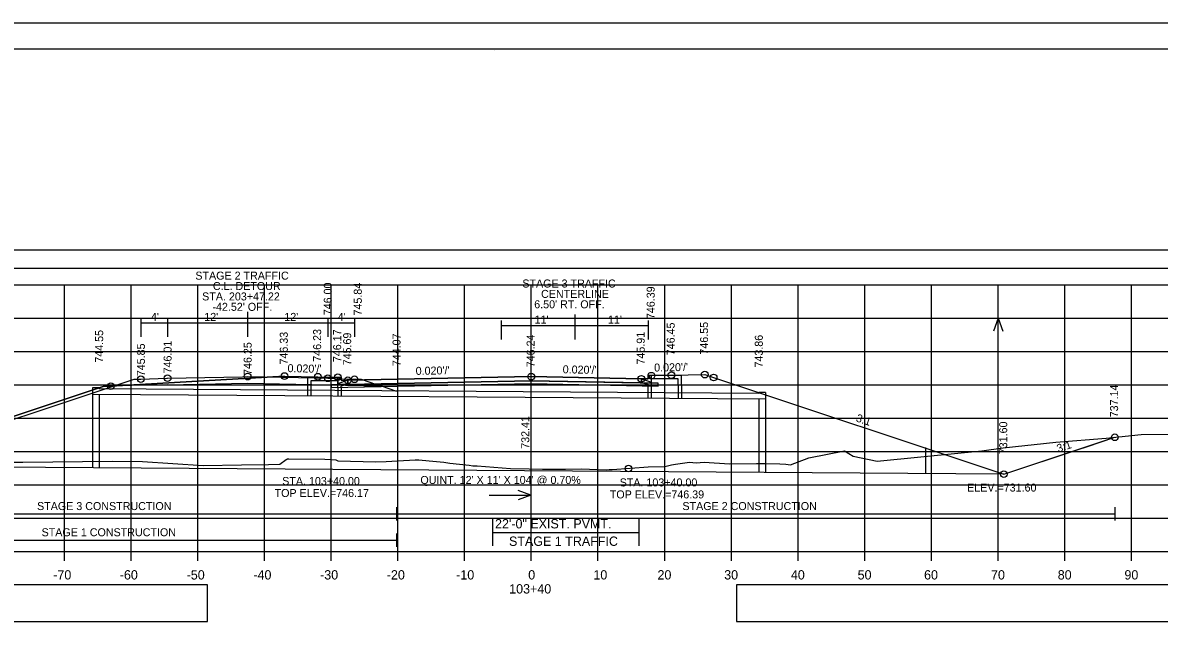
# Model space of a CAD drawing. Extents: x 1202951 to 1376887, y 378065 to 728038.
# Drawn here: x 1376508.4 to 1376678.8, y 378956.7 to 379047.8 of the extents above; entities that cross this region are included whole.
import ezdxf

# ---------------------------------------------------------------- set-up
doc = ezdxf.new("R2010")
doc.units = 0
for name, color, linetype in [('Default', 7, 'Continuous'), ('R_Alt Surface', 7, 'Continuous'), ('R_Axis', 7, 'Continuous'), ('R_Axis Annot', 7, 'Continuous'), ('R_Border', 7, 'Continuous'), ('R_Border Notes', 7, 'Continuous'), ('R_Detour', 7, 'Continuous'), ('R_Detour Annot', 7, 'Continuous'), ('R_Dimension', 7, 'Continuous'), ('R_Exist Surface', 7, 'Continuous'), ('R_Fin Surface', 7, 'Continuous'), ('R_Grid', 7, 'Continuous'), ('R_MOT', 7, 'Continuous'), ('R_No Plot', 7, 'Continuous'), ('R_Proposed Const Limits', 7, 'Continuous'), ('R_Water', 7, 'Continuous'), ('R_Water Annot', 7, 'Continuous'), ('R_Xsect Elev', 7, 'Continuous'), ('R_Xsect Slope', 7, 'Continuous')]:
    doc.layers.add(name, color=color, linetype=linetype)

msp = doc.modelspace()

# ---------------------------------------------------------------- linework, layer by layer
at = {"layer": 'Default'}
for points in [[(1376547.67, 378994.82), (1376521.65, 378993.29), (1376520.65, 378993.29), (1376484.65, 378981.29)], [(1376610.67, 378995.04), (1376612.01, 378994.6), (1376612.01, 378994.6), (1376655.52, 378980.09)]]:
    msp.add_lwpolyline(points, dxfattribs=at)
for points in [[(1376555.67, 378994.66), (1376556.16, 378994.66), (1376556.17, 378994.16), (1376557.17, 378994.18), (1376557.17, 378993.56), (1376555.67, 378993.53)], [(1376602.67, 378994.88), (1376602.18, 378994.88), (1376602.17, 378994.38), (1376601.17, 378994.4), (1376601.17, 378993.78), (1376602.67, 378993.75)]]:
    msp.add_lwpolyline(points, close=True, dxfattribs=at)
at = {"layer": 'R_Alt Surface'}
for q in [(1376554.67, 378993.51), (1376603.67, 378993.73)]:
    msp.add_line((1376584.67, 378994.11), q, dxfattribs=at)
for points in [[(1376434.67, 379010.99), (1376710.2, 379010.99), (1376710.2, 379013.7), (1376434.67, 379013.7)], [(1376584.67, 378994.11), (1376557.17, 378993.56), (1376555.67, 378993.53), (1376554.67, 378993.51), (1376554.67, 378993.09), (1376584.67, 378993.69), (1376603.67, 378993.31), (1376603.67, 378993.73), (1376602.67, 378993.75), (1376601.17, 378993.78)], [(1376557.17, 378994.18), (1376557.17, 378993.56), (1376584.67, 378994.11), (1376601.17, 378993.78), (1376601.17, 378994.4), (1376601.17, 378994.4), (1376584.67, 378994.73), (1376557.17, 378994.18)], [(1376434.67, 378957.97), (1376536.14, 378957.97), (1376536.14, 378963.49), (1376434.67, 378963.49)], [(1376615.43, 378957.97), (1376726.14, 378957.97), (1376726.14, 378963.49), (1376615.43, 378963.49)]]:
    msp.add_lwpolyline(points, close=True, dxfattribs=at)
msp.add_lwpolyline([(1376555.67, 378994.66), (1376555.67, 378993.53), (1376557.17, 378993.56), (1376584.67, 378994.11), (1376601.17, 378993.78), (1376602.67, 378993.75), (1376602.67, 378994.88)], dxfattribs=at)
at = {"layer": 'R_Axis'}
for p, q in [((1376434.67, 378968.49), (1376734.67, 378968.49)), ((1376514.67, 378967.09), (1376514.67, 378968.49)), ((1376524.67, 378967.09), (1376524.67, 378968.49)), ((1376534.67, 378967.09), (1376534.67, 378968.49)), ((1376544.67, 378967.09), (1376544.67, 378968.49)), ((1376554.67, 378967.09), (1376554.67, 378968.49)), ((1376564.67, 378967.09), (1376564.67, 378968.49)), ((1376574.67, 378967.09), (1376574.67, 378968.49)), ((1376584.67, 378967.09), (1376584.67, 378968.49)), ((1376594.67, 378967.09), (1376594.67, 378968.49)), ((1376604.67, 378967.09), (1376604.67, 378968.49)), ((1376614.67, 378967.09), (1376614.67, 378968.49)), ((1376624.67, 378967.09), (1376624.67, 378968.49)), ((1376634.67, 378967.09), (1376634.67, 378968.49)), ((1376644.67, 378967.09), (1376644.67, 378968.49)), ((1376654.67, 378967.09), (1376654.67, 378968.49)), ((1376664.67, 378967.09), (1376664.67, 378968.49)), ((1376674.67, 378967.09), (1376674.67, 378968.49))]:
    msp.add_line(p, q, dxfattribs=at)
at = {"layer": 'R_Border'}
for p, q in [((1376426.67, 379043.95), (1376742.85, 379043.95)), ((1376579.19, 379043.69), (1376579.19, 379043.69)), ((1376579.19, 379043.69), (1376579.19, 379043.69))]:
    msp.add_line(p, q, dxfattribs=at)
at = {"layer": 'R_Detour'}
for p, q in [((1376542.15, 379004.46), (1376542.15, 379000.7)), ((1376526.15, 379003.54), (1376526.15, 379000.7)), ((1376526.15, 379002.8), (1376530.15, 379002.8)), ((1376530.15, 379003.54), (1376530.15, 379000.7)), ((1376530.15, 379002.8), (1376542.15, 379002.8)), ((1376542.15, 379002.8), (1376554.15, 379002.8)), ((1376554.15, 379003.54), (1376554.15, 379000.7)), ((1376554.15, 379002.8), (1376558.15, 379002.8)), ((1376558.15, 379003.54), (1376558.15, 379000.7))]:
    msp.add_line(p, q, dxfattribs=at)
for points in [[(1376478.29, 378982.39), (1376480.46, 378981.67), (1376483.77, 378980.57), (1376494.76, 378984.23), (1376522.15, 378993.35), (1376524.97, 378994.29), (1376525.15, 378994.35), (1376526.1, 378994.35), (1376526.15, 378994.35), (1376530.06, 378994.5), (1376530.15, 378994.5), (1376532.95, 378994.56), (1376541.38, 378994.72), (1376542.15, 378994.74), (1376552.32, 378994.53), (1376554.16, 378994.49), (1376557.36, 378994.37), (1376558.16, 378994.33), (1376558.38, 378994.33), (1376559.16, 378994.33), (1376561.45, 378993.57), (1376562.17, 378993.33), (1376564.47, 378992.57)], [(1376530.15, 378993.5), (1376542.15, 378993.74), (1376554.16, 378993.49)], [(1376530.15, 378993.5), (1376522.15, 378993.35)], [(1376554.16, 378993.49), (1376562.17, 378993.33)]]:
    msp.add_lwpolyline(points, dxfattribs=at)
at = {"layer": 'R_Dimension'}
for points in [[(1376564.47, 378975.13), (1376564.47, 378973.13)], [(1376672.14, 378975.13), (1376672.14, 378973.13)], [(1376478.29, 378974.13), (1376564.47, 378974.13)], [(1376564.47, 378974.13), (1376672.14, 378974.13)], [(1376478.29, 378970.21), (1376564.47, 378970.21)], [(1376564.47, 378971.21), (1376564.47, 378969.21)]]:
    msp.add_lwpolyline(points, dxfattribs=at)
at = {"layer": 'R_Exist Surface'}
msp.add_lwpolyline([(1376505.03, 378981.9), (1376508.44, 378981.89), (1376521.91, 378982.03), (1376526.4, 378982), (1376535.5, 378981.41), (1376541.23, 378981.52), (1376545.28, 378981.57), (1376546.98, 378981.62), (1376547.93, 378982.3), (1376548.07, 378982.36), (1376548.09, 378982.39), (1376548.3, 378982.38), (1376553.72, 378982.36), (1376555.38, 378982.25), (1376555.68, 378982.11), (1376561.35, 378981.95), (1376562.93, 378982.01), (1376567.25, 378982.24), (1376567.82, 378982.25), (1376569.37, 378982.09), (1376571.56, 378981.88), (1376572.48, 378981.76), (1376575.36, 378981.43), (1376575.91, 378981.35), (1376576.32, 378981.36), (1376576.58, 378981.33), (1376581.55, 378980.94), (1376584.37, 378980.92), (1376586.35, 378980.85), (1376589.82, 378980.84), (1376592.13, 378980.88), (1376595.89, 378980.77), (1376596.36, 378980.8), (1376596.79, 378980.79), (1376597.47, 378980.84), (1376601.55, 378981.14), (1376602.21, 378981.19), (1376604.68, 378981.23), (1376605.71, 378981.5), (1376606.31, 378981.58), (1376608.4, 378981.91), (1376609.4, 378981.82), (1376610.58, 378981.88), (1376614.36, 378981.65), (1376618.41, 378981.68), (1376619.7, 378981.68), (1376621.95, 378981.66), (1376622.85, 378981.59), (1376623.52, 378981.49), (1376626.3, 378982.57), (1376631.61, 378983.61), (1376632.93, 378982.8), (1376636.51, 378982.03), (1376649.13, 378983.3), (1376652.19, 378983.58), (1376655.4, 378984.05), (1376663.33, 378984.9), (1376670.83, 378985.5), (1376676.12, 378986.05), (1376693.3, 378986.09)], dxfattribs=at)
at = {"layer": 'R_Fin Surface'}
for p, q in [((1376578.88, 378973.36), (1376578.88, 378969.36)), ((1376600.81, 378973.36), (1376600.81, 378969.36)), ((1376578.88, 378971.36), (1376600.81, 378971.36))]:
    msp.add_line(p, q, dxfattribs=at)
for points in [[(1376481.09, 378982.48), (1376484.65, 378981.29), (1376520.65, 378993.29), (1376521.65, 378993.29), (1376547.67, 378994.82), (1376552.67, 378994.72), (1376555.67, 378994.66), (1376556.16, 378994.66), (1376556.17, 378994.16), (1376557.17, 378994.18), (1376584.67, 378994.73), (1376601.17, 378994.4), (1376602.17, 378994.38), (1376602.18, 378994.88), (1376602.67, 378994.88), (1376605.67, 378994.94), (1376610.67, 378995.04), (1376612.01, 378994.6), (1376655.52, 378980.09), (1376666.82, 378983.86), (1376667.73, 378984.16), (1376667.88, 378984.21), (1376672.14, 378985.63)], [(1376547.67, 378994.82), (1376552.67, 378994.72), (1376555.67, 378994.66), (1376556.16, 378994.66), (1376556.17, 378994.16), (1376557.17, 378994.18), (1376557.17, 378994.18), (1376584.67, 378994.73), (1376601.17, 378994.4), (1376601.17, 378994.4), (1376602.17, 378994.38), (1376602.18, 378994.88), (1376602.67, 378994.88), (1376605.67, 378994.94), (1376610.67, 378995.04)]]:
    msp.add_lwpolyline(points, dxfattribs=at)
at = {"layer": 'R_Grid'}
for p, q in [((1376434.67, 379008.49), (1376734.67, 379008.49)), ((1376514.67, 378968.49), (1376514.67, 379008.49)), ((1376524.67, 378968.49), (1376524.67, 379008.49)), ((1376534.67, 378968.49), (1376534.67, 379008.49)), ((1376544.67, 378968.49), (1376544.67, 379008.49)), ((1376554.67, 378968.49), (1376554.67, 379008.49)), ((1376564.67, 378968.49), (1376564.67, 379008.49)), ((1376574.67, 378968.49), (1376574.67, 379008.49)), ((1376584.67, 378968.49), (1376584.67, 379008.49)), ((1376594.67, 378968.49), (1376594.67, 379008.49)), ((1376604.67, 378968.49), (1376604.67, 379008.49)), ((1376614.67, 378968.49), (1376614.67, 379008.49)), ((1376624.67, 378968.49), (1376624.67, 379008.49)), ((1376634.67, 378968.49), (1376634.67, 379008.49)), ((1376644.67, 378968.49), (1376644.67, 379008.49)), ((1376654.67, 378968.49), (1376654.67, 379008.49)), ((1376664.67, 378968.49), (1376664.67, 379008.49)), ((1376674.67, 378968.49), (1376674.67, 379008.49)), ((1376434.67, 379003.49), (1376734.67, 379003.49)), ((1376434.67, 378998.49), (1376734.67, 378998.49)), ((1376434.67, 378993.49), (1376734.67, 378993.49)), ((1376434.67, 378988.49), (1376734.67, 378988.49)), ((1376434.67, 378983.49), (1376734.67, 378983.49)), ((1376434.67, 378978.49), (1376734.67, 378978.49)), ((1376434.67, 378973.49), (1376734.67, 378973.49)), ((1376434.67, 378968.49), (1376734.67, 378968.49))]:
    msp.add_line(p, q, dxfattribs=at)
at = {"layer": 'R_MOT'}
for p, q in [((1376591.18, 379004.06), (1376591.18, 379000.3)), ((1376580.18, 379003.15), (1376580.18, 379000.3)), ((1376580.18, 379002.4), (1376591.18, 379002.4)), ((1376591.18, 379002.4), (1376602.18, 379002.4)), ((1376602.18, 379003.15), (1376602.18, 379000.3))]:
    msp.add_line(p, q, dxfattribs=at)
at = {"layer": 'R_No Plot'}
msp.add_line((1376414.27, 379047.85), (1376747.6, 379047.85), dxfattribs=at)
for points in [[(1376414.26, 379047.85), (1376747.6, 379047.85), (1376747.6, 378834.51), (1376414.26, 378834.51)], [(1376660.59, 379043.95), (1376680.21, 379043.95), (1376680.21, 379034.07), (1376696.32, 379034.07), (1376719.52, 379034.07), (1376719.64, 379005.92), (1376742.85, 379005.92), (1376742.85, 378838.49), (1376426.67, 378838.49), (1376426.67, 379043.95)]]:
    msp.add_lwpolyline(points, close=True, dxfattribs=at)
for centre in [(1376542.15, 378994.74), (1376547.67, 378994.82), (1376547.67, 378994.82), (1376552.67, 378994.72), (1376552.67, 378994.72), (1376584.67, 378994.73), (1376584.67, 378994.73), (1376602.67, 378994.88), (1376602.67, 378994.88), (1376605.67, 378994.94), (1376605.67, 378994.94), (1376610.67, 378995.04), (1376610.67, 378995.04), (1376521.65, 378993.29), (1376526.15, 378994.35), (1376530.15, 378994.5), (1376554.16, 378994.49), (1376555.67, 378994.66), (1376555.67, 378994.66), (1376557.17, 378994.18), (1376557.17, 378994.18), (1376558.16, 378994.33), (1376601.17, 378994.4), (1376601.17, 378994.4), (1376612.01, 378994.6), (1376672.14, 378985.63), (1376672.14, 378985.63), (1376599.23, 378980.96), (1376599.23, 378980.96), (1376599.23, 378980.96), (1376655.52, 378980.09), (1376655.52, 378980.09)]:
    msp.add_circle(centre, 0.5, dxfattribs=at)
at = {"layer": 'R_Proposed Const Limits'}
msp.add_lwpolyline([(1376655.52, 378980.09), (1376672.14, 378985.63)], dxfattribs=at)
at = {"layer": 'R_Water'}
for p, q in [((1376551.17, 378994.66), (1376555.92, 378994.66)), ((1376551.17, 378993.16), (1376551.17, 378994.66)), ((1376551.67, 378993.16), (1376551.67, 378994.16)), ((1376551.67, 378994.16), (1376555.67, 378994.16)), ((1376556, 378994.5), (1376555.67, 378994.16)), ((1376557.17, 378994.18), (1376555.67, 378993.66)), ((1376555.67, 378993.16), (1376555.67, 378993.66)), ((1376556, 378994.5), (1376555.92, 378994.66)), ((1376557.17, 378993.65), (1376556.17, 378993.31)), ((1376601.17, 378994.4), (1376602.67, 378993.88)), ((1376601.17, 378993.87), (1376602.17, 378993.53)), ((1376602.17, 378993.38), (1376602.17, 378993.53)), ((1376602.34, 378994.72), (1376602.42, 378994.88)), ((1376602.34, 378994.72), (1376602.67, 378994.38)), ((1376607.17, 378994.88), (1376602.42, 378994.88)), ((1376606.67, 378994.38), (1376602.67, 378994.38)), ((1376602.67, 378993.38), (1376602.67, 378993.88)), ((1376606.67, 378993.38), (1376606.67, 378994.38)), ((1376607.17, 378993.38), (1376607.17, 378994.88)), ((1376519.89, 378993.05), (1376518.89, 378993.05)), ((1376518.89, 378993.05), (1376518.89, 378981.05)), ((1376619.78, 378991.35), (1376518.89, 378992.05)), ((1376519.89, 378993.05), (1376519.89, 378992.88)), ((1376618.78, 378992.19), (1376519.89, 378992.88)), ((1376519.89, 378992.05), (1376519.89, 378981.05)), ((1376551.17, 378991.83), (1376551.17, 378993.16)), ((1376551.67, 378991.82), (1376551.67, 378993.16)), ((1376555.67, 378993.16), (1376555.67, 378991.8)), ((1376556.17, 378993.16), (1376556.17, 378993.31)), ((1376556.17, 378993.16), (1376556.17, 378991.79)), ((1376602.17, 378991.47), (1376602.17, 378993.38)), ((1376602.67, 378991.47), (1376602.67, 378993.38)), ((1376606.67, 378993.38), (1376606.67, 378991.44)), ((1376607.17, 378993.38), (1376607.17, 378991.43)), ((1376618.78, 378992.35), (1376618.78, 378992.19)), ((1376619.78, 378992.35), (1376618.78, 378992.35)), ((1376619.78, 378992.35), (1376619.78, 378980.35)), ((1376618.78, 378991.35), (1376618.78, 378980.35)), ((1376643.78, 378984.12), (1376643.78, 378980.18)), ((1376655.51, 378980.09), (1376484.65, 378981.29))]:
    msp.add_line(p, q, dxfattribs=at)
for points in [[(1376557.17, 378993.65), (1376557.17, 378994.18)], [(1376601.17, 378993.87), (1376601.17, 378994.4)]]:
    msp.add_lwpolyline(points, dxfattribs=at)
at = {"layer": 'R_Water Annot'}
for p, q in [((1376654.67, 379003.49), (1376653.97, 379001.57)), ((1376654.67, 378997.21), (1376654.67, 379003.49)), ((1376654.67, 379003.49), (1376655.37, 379001.57)), ((1376578.34, 378976.96), (1376584.62, 378976.96)), ((1376584.62, 378976.96), (1376582.7, 378977.66)), ((1376584.62, 378976.96), (1376582.7, 378976.26))]:
    msp.add_line(p, q, dxfattribs=at)
at = {"layer": 'R_Xsect Elev'}
msp.add_line((1376584.67, 378980.91), (1376584.67, 378990.91), dxfattribs=at)

# ---------------------------------------------------------------- texts
at = {"layer": 'R_Axis Annot'}
for s, p in [('22\'-0" EXIST. PVMT.', (1376579.24, 378971.96)), ('STAGE 1 TRAFFIC', (1376581.33, 378969.34)), ('-70', (1376513.01, 378964.29)), ('-60', (1376522.98, 378964.29)), ('-50', (1376533.01, 378964.29)), ('-40', (1376543.01, 378964.29)), ('-30', (1376553.01, 378964.29)), ('-20', (1376563.01, 378964.29)), ('-10', (1376573.41, 378964.29)), ('0', (1376584.21, 378964.29)), ('10', (1376593.98, 378964.29)), ('20', (1376603.59, 378964.29)), ('30', (1376613.59, 378964.29)), ('40', (1376623.59, 378964.29)), ('50', (1376633.59, 378964.29)), ('60', (1376643.55, 378964.29)), ('70', (1376653.59, 378964.29)), ('80', (1376663.59, 378964.29)), ('90', (1376673.59, 378964.29)), ('103+40', (1376581.36, 378962.19))]:
    msp.add_text(s, height=1.4, dxfattribs=at).set_placement(p)
at = {"layer": 'R_Border Notes'}
msp.add_text('ELEV.=731.60', height=1.2, dxfattribs=at).set_placement((1376650.01, 378977.49))
at = {"layer": 'R_Detour'}
for s, p in [('STAGE 2 TRAFFIC', (1376534.31, 379009.29)), ('C.L. DETOUR', (1376536.94, 379007.73)), ('STA. 203+47.22', (1376535.33, 379006.17)), ("-42.52' OFF.", (1376536.87, 379004.61)), ("4'", (1376527.65, 379003.1)), ("12'", (1376535.65, 379003.1)), ("12'", (1376547.65, 379003.1)), ("4'", (1376555.65, 379003.1))]:
    msp.add_text(s, height=1.2, dxfattribs=at).set_placement(p)
at = {"layer": 'R_Detour Annot'}
for s, p in [('746.00', (1376554.76, 379003.95)), ('745.84', (1376559.26, 379003.91)), ('744.07', (1376565.07, 378996.3)), ('745.85', (1376526.75, 378994.8)), ('746.01', (1376530.75, 378995.22)), ('746.25', (1376542.75, 378994.99))]:
    msp.add_text(s, height=1.2, rotation=90, dxfattribs=at).set_placement(p)
at = {"layer": 'R_Dimension'}
for s, p in [('STAGE 3 CONSTRUCTION', (1376510.58, 378974.71)), ('STAGE 2 CONSTRUCTION', (1376607.33, 378974.71)), ('STAGE 1 CONSTRUCTION', (1376511.26, 378970.78))]:
    msp.add_text(s, height=1.2, dxfattribs=at).set_placement(p)
at = {"layer": 'R_MOT'}
for s, p in [('STAGE 3 TRAFFIC ', (1376583.33, 379008.11)), ('CENTERLINE', (1376586.14, 379006.55)), ("6.50' RT. OFF.", (1376585.11, 379004.99)), ("11'", (1376585.17, 379002.7)), ("11'", (1376596.17, 379002.7))]:
    msp.add_text(s, height=1.2, dxfattribs=at).set_placement(p)
at = {"layer": 'R_Water Annot'}
for s, p in [("QUINT. 12' X 11' X 104' @ 0.70%", (1376568.05, 378978.63)), ('STA. 103+40.00', (1376547.33, 378978.47)), ('STA. 103+40.00', (1376597.92, 378978.26)), ('TOP ELEV.=746.17', (1376546.19, 378976.67)), ('TOP ELEV.=746.39', (1376596.44, 378976.46))]:
    msp.add_text(s, height=1.2, rotation=360, dxfattribs=at).set_placement(p)
at = {"layer": 'R_Xsect Elev'}
for s, p in [('746.39', (1376603.17, 379003.37)), ('746.45', (1376606.17, 378997.94)), ('746.45', (1376606.17, 378997.94)), ('746.55', (1376611.17, 378998.04)), ('746.55', (1376611.17, 378998.04)), ('744.55', (1376520.49, 378996.83)), ('746.33', (1376548.17, 378996.55)), ('746.23', (1376553.17, 378996.97)), ('746.17', (1376556.17, 378996.91)), ('745.69', (1376557.67, 378996.43)), ('746.24', (1376585.17, 378996.14)), ('745.91', (1376601.67, 378996.55)), ('743.86', (1376619.38, 378996.1)), ('737.14', (1376672.64, 378988.63)), ('737.14', (1376672.64, 378988.63)), ('732.41', (1376584.37, 378983.91)), ('731.60', (1376656.02, 378983.09)), ('731.60', (1376656.02, 378983.09))]:
    msp.add_text(s, height=1.2, rotation=90, dxfattribs=at).set_placement(p)
at = {"layer": 'R_Xsect Slope'}
for s, rotation, p in [("0.020'/'", 358.8542, (1376548.12, 378995.41)), ("0.020'/'", 1.1458, (1376567.35, 378994.99)), ("0.020'/'", 358.8542, (1376589.37, 378995.24)), ("0.020'/'", 1.1458, (1376603.1, 378995.49)), ('3:1', 341.5651, (1376633.25, 378988.04)), ('3:1', 18.4349, (1376663.67, 378983.34))]:
    msp.add_text(s, height=1.2, rotation=rotation, dxfattribs=at).set_placement(p)

doc.saveas('drawing.dxf')
